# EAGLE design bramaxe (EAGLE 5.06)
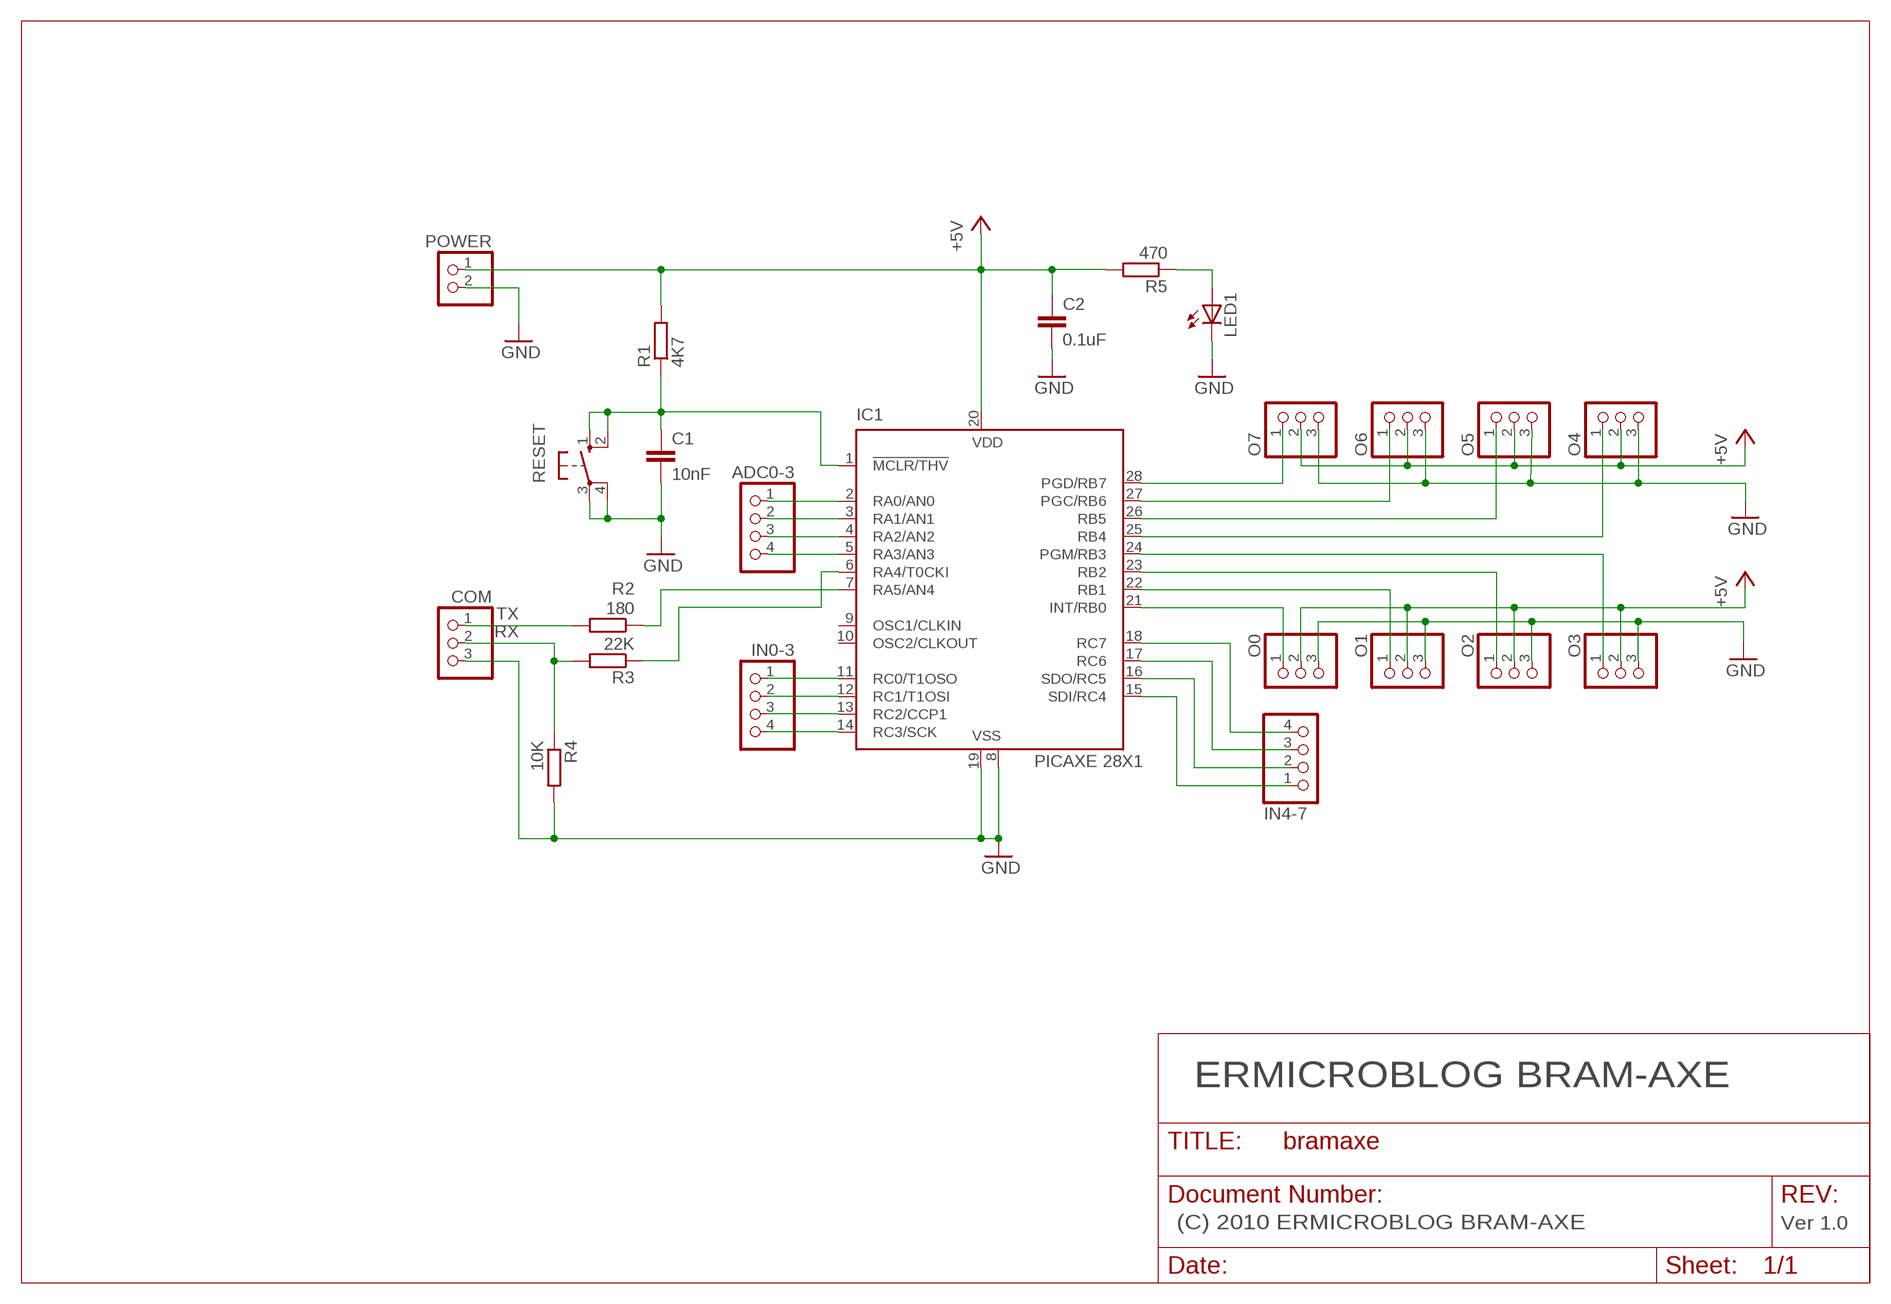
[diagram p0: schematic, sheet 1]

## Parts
ADC0-3  PINHD-1X4  [1X04]
C1  10nF  C-EU050-024X044  [C050-024X044]
C2  0.1uF  C-EU050-024X044  [C050-024X044]
COM  PINHD-1X3  [1X03]
IC1  PICAXE 28X1  PIC16F872P  [DIL28-3]
IN0-3  PINHD-1X4  [1X04]
IN4-7  PINHD-1X4  [1X04]
LED1  LED3MM  [LED3MM]
O0  PINHD-1X3  [1X03]
O1  PINHD-1X3  [1X03]
O2  PINHD-1X3  [1X03]
O3  PINHD-1X3  [1X03]
O4  PINHD-1X3  [1X03]
O5  PINHD-1X3  [1X03]
O6  PINHD-1X3  [1X03]
O7  PINHD-1X3  [1X03]
POWER  PINHD-1X2  [1X02]
R1  4K7  R-EU_0207/10  [0207/10]
R2  180  R-EU_0207/10  [0207/10]
R3  22K  R-EU_0207/10  [0207/10]
R4  10K  R-EU_0207/10  [0207/10]
R5  470  R-EU_0207/10  [0207/10]
RESET  10-XX  [B3F-10XX]

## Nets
+5V: C2.1 IC1.20(VDD) O0.2 O1.2 O2.2 O3.2 O4.2 O5.2 O6.2 O7.2 POWER.1 R1.2 R5.2
GND: C1.2 C2.2 COM.3 IC1.8(VSS) IC1.19(VSS) LED1.K(C) O0.3 O1.3 O2.3 O3.3 O4.3 O5.3 O6.3 O7.3 POWER.2 R4.2 RESET.3(P) RESET.4(P1)
N$1: IC1.28(PGD/RB7) O7.1
N$2: C1.1 IC1.1(!MCLR/THV) R1.1 RESET.1(S) RESET.2(S1)
N$3: IC1.27(PGC/RB6) O6.1
N$4: IC1.26(RB5) O5.1
N$5: IC1.7(RA5/AN4) R2.1
N$6: IC1.6(RA4/T0CKI) R3.1
N$7: IC1.25(RB4) O4.1
N$8: IC1.18(RC7) IN4-7.4
N$9: IC1.17(RC6) IN4-7.3
N$10: IC1.16(SDO/RC5) IN4-7.2
N$11: IC1.15(SDI/RC4) IN4-7.1
N$12: IC1.11(RC0/T1OSO) IN0-3.1
N$13: ADC0-3.1 IC1.2(RA0/AN0)
N$14: ADC0-3.2 IC1.3(RA1/AN1)
N$15: ADC0-3.3 IC1.4(RA2/AN2)
N$16: ADC0-3.4 IC1.5(RA3/AN3)
N$17: IC1.12(RC1/T1OSI) IN0-3.2
N$18: IC1.13(RC2/CCP1) IN0-3.3
N$19: IC1.14(RC3/SCK) IN0-3.4
N$20: IC1.24(PGM/RB3) O3.1
N$21: IC1.23(RB2) O2.1
N$22: IC1.22(RB1) O1.1
N$23: IC1.21(INT/RB0) O0.1
N$24: LED1.A R5.1
RX: COM.2 R3.2 R4.1
TX: COM.1 R2.2
Unconnected: IC1.9(OSC1/CLKIN) IC1.10(OSC2/CLKOUT)

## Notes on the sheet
- ERMICROBLOG BRAM-AXE
- (C) 2010 ERMICROBLOG BRAM-AXE | Ver 1.0

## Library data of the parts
ADC0-3 IN0-3 IN4-7 = pinhead:PINHD-1X4: PIN HEADER
C1 C2 = rcl:C-EU: CAPACITOR, European symbol
COM O0 O1-O7 = pinhead:PINHD-1X3: PIN HEADER
IC1 = microchip:PIC16*872: MICROCONTROLLER flash type
LED1 = led:LED: LED
POWER = pinhead:PINHD-1X2: PIN HEADER
R1-R5 = rcl:R-EU_: RESISTOR, European symbol
RESET = switch-omron:10-XX: OMRON SWITCH

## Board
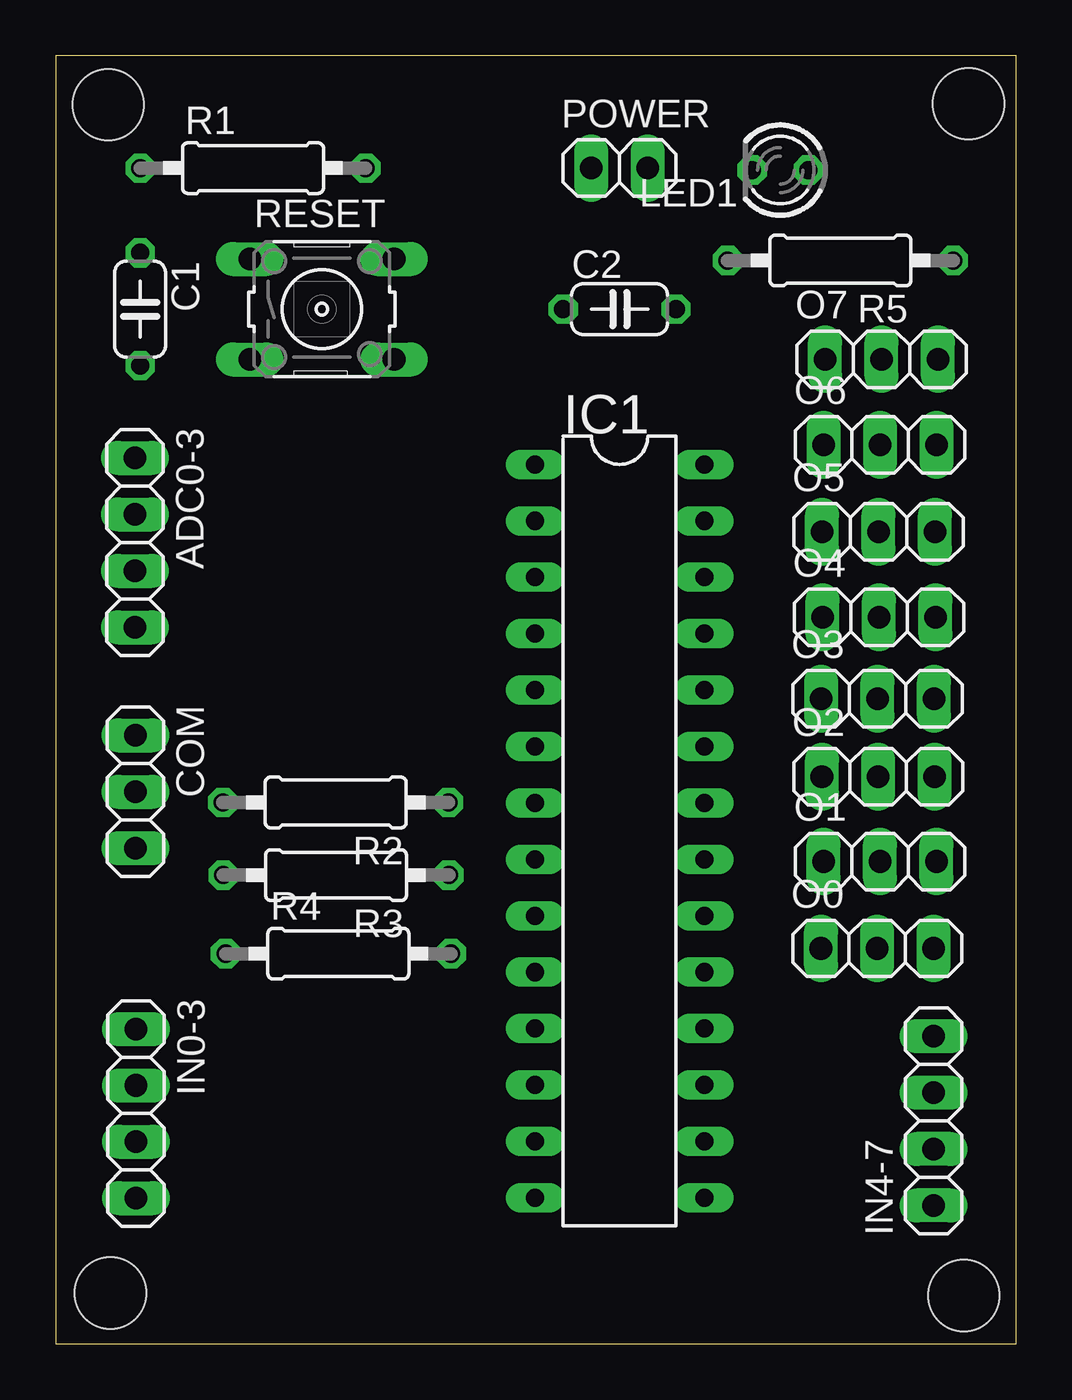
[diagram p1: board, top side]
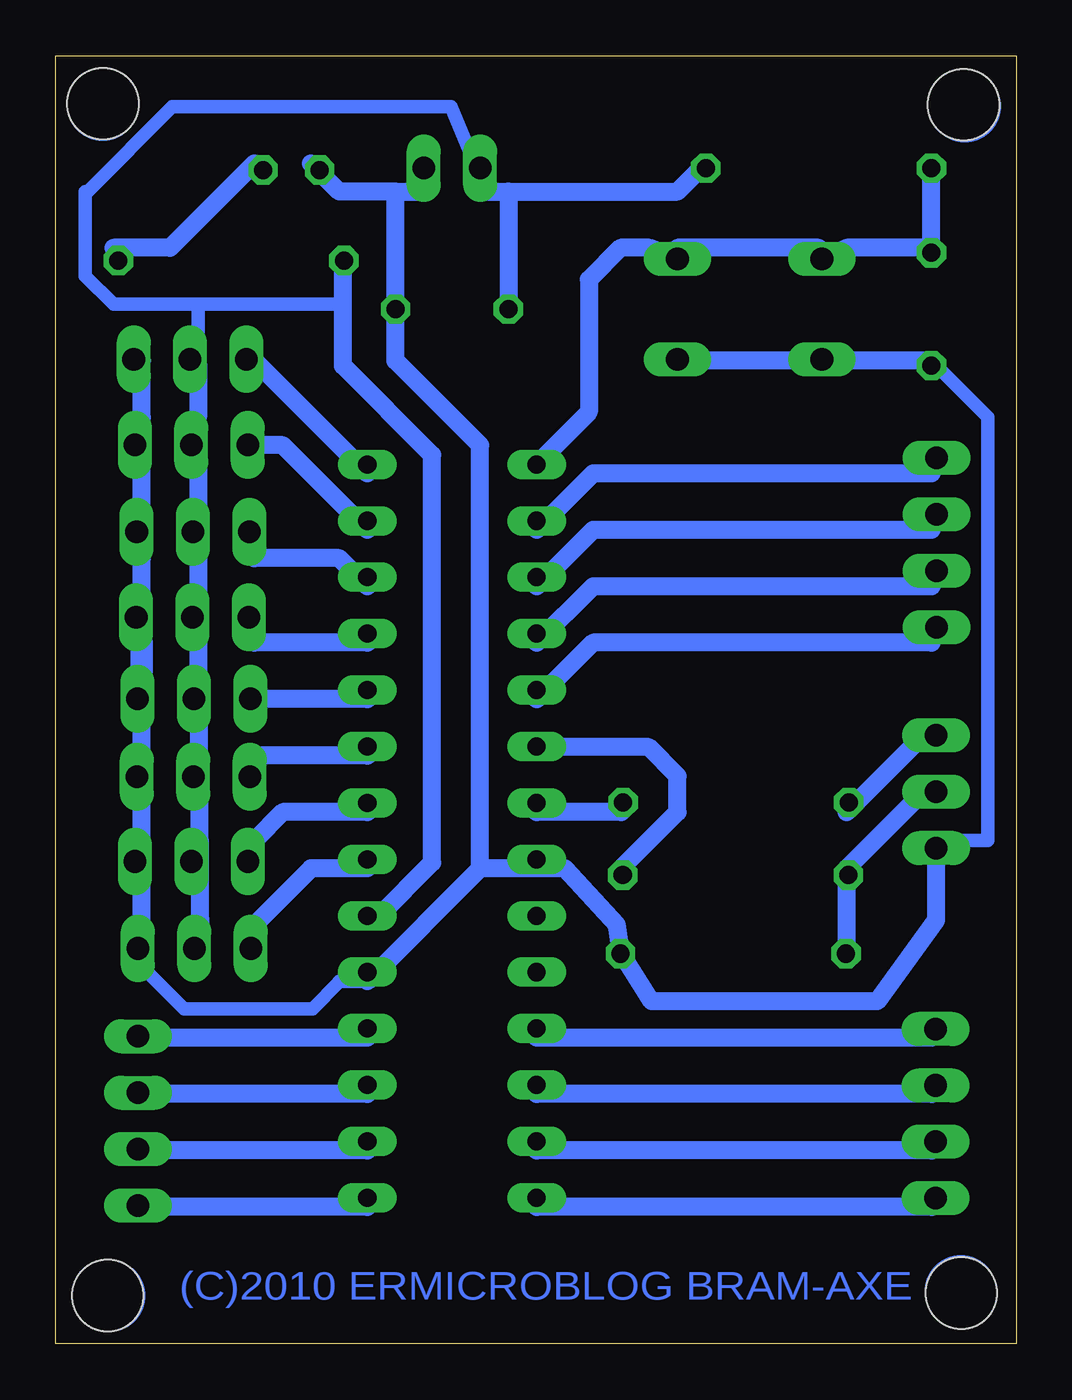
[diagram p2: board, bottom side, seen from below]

Size 43.25 x 58.01 mm. Coordinates in mm from the lower left corner, seen from the top.
Outline: 0,0 43.25,0 43.25,58.01 0,58.01 0,0
Copper layers (1*16): Top 0.035mm / dielectric 1.5mm / Bottom 0.035mm
Design rules "default *": minimum track width 18mil, minimum drill 24mil, track to track 8mil, track to pad 8mil, pad to pad 8mil, via to via 8mil, smd to smd 8mil, copper to edge 40mil, drill to drill 8mil, minimum pad ring 10mil, minimum via ring 8mil, stop-mask expansion 4mil, vias tented up to drill 0mil, thermal gap 10mil
Holes 3.2 mm at 41.12,55.84 2.37,55.8 40.9,2.18 2.47,2.29
tRestrict: area 0.2,0.1 to 43.1,55.5

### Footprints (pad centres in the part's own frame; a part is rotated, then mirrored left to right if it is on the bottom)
1X04 = drill 1.016 long: 1 -3.81,0; 2 -1.27,0; 3 1.27,0; 4 3.81,0
C050-024X044 = drill 0.813 octagon: 1 -2.54,0; 2 2.54,0
1X03 = drill 1.016 long: 1 -2.54,0; 2 0,0; 3 2.54,0
DIL28-3 = drill 0.813 long: 1 -16.51,-3.81; 2 -13.97,-3.81; 3 -11.43,-3.81; 4 -8.89,-3.81; 5 -6.35,-3.81; 6 -3.81,-3.81; 7 -1.27,-3.81; 8 1.27,-3.81; 9 3.81,-3.81; 10 6.35,-3.81; 11 8.89,-3.81; 12 11.43,-3.81; 13 13.97,-3.81; 14 16.51,-3.81; 15 16.51,3.81; 16 13.97,3.81; 17 11.43,3.81; 18 8.89,3.81; 19 6.35,3.81; 20 3.81,3.81; 21 1.27,3.81; 22 -1.27,3.81; 23 -3.81,3.81; 24 -6.35,3.81; 25 -8.89,3.81; 26 -11.43,3.81; 27 -13.97,3.81; 28 -16.51,3.81
LED3MM = drill 0.813 octagon: A -1.27,0; K 1.27,0
1X02 = drill 1.016 long: 1 -1.27,0; 2 1.27,0
0207/10 = drill 0.813 octagon: 1 -5.08,0; 2 5.08,0
B3F-10XX = drill 1.016 long: 1 -3.251,2.261; 2 3.251,2.261; 3 -3.251,-2.261; 4 3.251,-2.261

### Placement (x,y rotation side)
ADC0-3  3.58,36.08 270 top
C1  3.81,46.59 270 top
C2  25.4,46.59 0 top
COM  3.59,24.86 270 top
IC1  25.4,23.09 270 top
IN0-3  3.62,10.37 270 top
IN4-7  39.54,10.04 90 top
LED1  32.63,52.86 180 top
O0  37,17.81 0 top
O1  37.13,21.72 0 top
O2  37.05,25.54 0 top
O3  37.02,29.05 0 top
O4  37.08,32.72 0 top
O5  37.06,36.56 0 top
O6  37.14,40.49 0 top
O7  37.19,44.34 0 top
POWER  25.4,52.94 0 top
R1  8.89,52.94 0 top
R2  12.62,24.38 180 top
R3  12.63,21.11 180 top
R4  12.74,17.57 0 top
R5  35.34,48.78 180 top
RESET  11.99,46.59 0 top

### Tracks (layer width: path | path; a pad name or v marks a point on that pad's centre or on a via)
+5V
  Bottom 0.406: 30.31,48.74 R5.2 | 36.86,46.81 36.83,46.78 | 36.83,44.14 37.03,44.34
  Bottom 0.457: 36.83,31.57 O4.2 36.83,32.84 | 36.74,17.45 O3.2 36.83,29.03 36.83,26.49 O2.2 36.83,25.22 36.83,22.68 O1.2 36.83,21.41 36.83,18.87 O0.2 | 36.83,35.38 O5.2 36.83,36.65 | O6.2 36.83,40.46 | 36.83,44.14 36.83,44.27 | 13.97,53.16 R1.2 | 41.91,51.89 41.81,51.89 | 24.39,53.16 POWER.1
  Bottom 0.61: 30.31,46.81 36.86,46.81 40.64,46.81 41.91,48.08 41.91,51.89 | 41.81,51.89 38,55.7 25.45,55.7 24.39,53.16 | 36.83,46.78 36.83,44.14
  Bottom 0.813: 36.83,31.57 36.74,17.45 | 36.83,35.38 36.83,32.84 | 36.83,40.46 36.83,36.65 | IC1.20 28.68,19.28 26.29,21.67 26.29,40.03 30.31,44.05 30.31,46.81 30.31,48.74 | 36.83,44.14 36.83,41.73 O6.2 | 22.86,51.89 24.13,51.89 POWER.1 | 22.86,51.89 C2.1 | 13.97,53.16 15.24,51.89 22.86,51.89 | 37.03,44.34 O7.2
GND
  Bottom 0.406: 30.48,16.33 30.48,16.3 | 39.66,17.29 39.66,17.7 O0.3 | O4.3 39.37,32.72
  Bottom 0.457: 39.37,21.41 O1.3 | 39.37,29.03 O3.3 | 39.37,25.22 O2.3 | 15.24,44.27 RESET.4 | RESET.3 8.89,44.27 | 31.75,53.16 LED1.K | 3.81,44.27 C1.2 | COM.3 2.54,22.68 | O0.3 39.37,17.6 | 17.78,17.6 R4.2 | O4.3 39.37,32.84 | 39.37,40.46 O6.3 | O5.3 39.37,36.65
  Bottom 0.61: 3.81,44.27 1.27,41.73 1.27,22.68 2.54,22.68 | 29.21,16.33 30.48,16.33 | 30.48,16.3 31.69,15.09 37.46,15.09 39.66,17.29
  Bottom 0.813: 39.37,21.41 39.37,18.87 O0.3 | O3.3 39.37,30.3 | 39.37,29.03 39.37,26.49 O2.3 | 39.37,25.22 39.37,22.68 O1.3 | 3.81,44.27 7.62,44.27 RESET.3 | 8.89,44.27 15.24,44.27 | 27.94,51.89 26.67,51.89 POWER.2 | 31.75,53.16 30.48,51.89 27.94,51.89 | 21.59,21.41 20.32,21.41 17.98,18.87 17.78,17.6 16.41,15.43 6.25,15.43 3.59,19.09 COM.3 | 24.13,21.41 29.21,16.33 IC1.19 | 21.59,21.41 24.13,21.41 | 21.59,21.41 IC1.8 | 24.13,21.41 24.13,40.46 27.94,44.27 C2.2 27.94,51.89 | O6.3 39.37,41.73 39.37,44.27 O7.3 | 39.37,32.84 39.37,35.38 O5.3 | 39.37,36.65 39.37,40.46 | 39.37,32.72 39.37,31.57
  Bottom 1.016: 39.37,30.3 39.37,31.57
N$1
  Bottom 0.813: IC1.28 29.21,39.19 34.29,44.27 O7.1
N$2
  Bottom 0.457: R1.1 3.81,53.16 | C1.1 3.81,49.35 | IC1.1 21.59,39.19
  Bottom 0.813: R1.1 3.81,49.35 7.62,49.35 RESET.1 8.89,49.35 15.24,49.35 RESET.2 16.51,49.35 17.81,49.35 19.23,47.93 19.23,41.96 IC1.1
N$3
  Bottom 0.813: IC1.27 29.21,36.65 33.02,40.46 34.29,40.46 O6.1
N$4
  Bottom 0.813: IC1.26 29.21,34.11 30.48,35.38 34.29,35.38 O5.1
N$5
  Bottom 0.457: R2.1 17.78,23.95
  Bottom 0.813: 17.78,23.95 21.59,23.95 IC1.7
N$6
  Bottom 0.406: 21.56,26.87 IC1.6
  Bottom 0.457: R3.1 17.78,21.41 | IC1.6 21.59,26.49
  Bottom 0.813: 17.78,21.41 15.24,23.95 15.24,25.57 16.54,26.87 21.56,26.87
N$7
  Bottom 0.813: IC1.25 29.21,31.57 34.29,31.57 O4.1
N$8
  Bottom 0.406: 39.48,13.79 IN4-7.4
  Bottom 0.457: IN4-7.4 39.37,13.79
  Bottom 0.813: IC1.18 29.21,13.79 39.48,13.79
N$9
  Bottom 0.457: 39.37,11.25 IN4-7.3
  Bottom 0.813: 39.37,11.25 29.21,11.25 IC1.17
N$10
  Bottom 0.457: 39.37,8.71 IN4-7.2
  Bottom 0.813: 39.37,8.71 29.21,8.71 IC1.16
N$11
  Bottom 0.457: 39.37,6.17 IN4-7.1
  Bottom 0.813: 39.37,6.17 29.21,6.17 IC1.15
N$12
  Bottom 0.813: IC1.11 21.59,13.79 3.81,13.79 IN0-3.1
N$13
  Bottom 0.813: IC1.2 21.59,36.65 19.05,39.19 3.81,39.19 ADC0-3.1
N$14
  Bottom 0.813: IC1.3 21.59,34.11 19.05,36.65 3.81,36.65 ADC0-3.2
N$15
  Bottom 0.813: IC1.4 21.59,31.57 19.05,34.11 3.81,34.11 ADC0-3.3
N$16
  Bottom 0.813: IC1.5 21.59,29.03 19.05,31.57 3.81,31.57 ADC0-3.4
N$17
  Bottom 0.813: IC1.12 21.59,11.25 3.81,11.25 IN0-3.2
N$18
  Bottom 0.813: IC1.13 21.59,8.71 3.81,8.71 IN0-3.3
N$19
  Bottom 0.813: IC1.14 21.59,6.17 3.81,6.17 IN0-3.4
N$20
  Bottom 0.457: 34.29,29.03 O3.1
  Bottom 0.813: 34.29,29.03 29.21,29.03 IC1.24
N$21
  Bottom 0.813: IC1.23 29.21,26.49 34.29,26.49 O2.1
N$22
  Bottom 0.813: IC1.22 29.21,23.95 33.02,23.95 34.29,22.68 O1.1
N$23
  Bottom 0.813: IC1.21 29.21,21.41 31.75,21.41 34.29,18.87 O0.1
N$24
  Bottom 0.813: LED1.A 34.29,53.16 38.1,49.35 40.64,49.35 R5.1
RX
  Bottom 0.457: R4.1 7.62,17.6 | 7.62,21.41 R3.2
  Bottom 0.813: 7.62,17.6 7.62,21.41 3.81,25.22 COM.2
TX
  Bottom 0.457: R2.2 7.62,23.95
  Bottom 0.813: 7.62,23.95 3.81,27.76 COM.1
(copper drawn outside any net)
  shapes: Bottom circle x4

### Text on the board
Bottom: (C)2010 ERMICROBLOG BRAM-AXE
